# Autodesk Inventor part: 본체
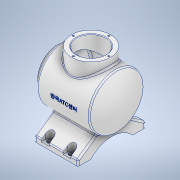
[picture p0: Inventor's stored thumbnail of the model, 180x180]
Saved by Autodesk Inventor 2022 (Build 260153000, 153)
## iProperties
Created: 2023-04
Part Number: 본체
Material: 알루미늄 6061
Document SubType Name: Modeling
Designer: Admin
Mass: 1296.69 g
Surface Area: 1060.41 cm^2
Volume: 480.256 cm^3
Density: 2.7 g/cm^3
Appearance: 알루미늄 - 평지
Author: Admin
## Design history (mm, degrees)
sketch "스케치1"
  geometry: L1 (-84.575, 0)-(87.453, 0) reference; L2 (0, -24.969)-(0, 149.813) reference; L3 (-60, 0)-(-60, 36); L4 (-60, 36)-(-48, 36); L5 (-48, 36)-(-48, 50); L6 (-48, 50)-(48.336, 50); L7 (60, 0)-(60, 124.844); L8 (-60, 0)-(60, 0); A1 r 113 centre (-53, 0) between (60, 0) and (48.336, 50); 1 further point
  constraints: 12 end point, 2 perpendicular, 2 point on circle, 2 point on line, 2 vertical, 1 centre point, 1 collinear, 1 horizontal, 1 tangent, 1 other
  dimensions: "d2" = 226 diameter of A1; "d3" = 120 distance from line of L7.start L3; "d4" = 108 distance from line of L7.start L5; "d5" = 72 diameter of L4 L1; "d6" = 100 diameter of L6 L1
revolve "회전1" sketch "스케치1" stored, may be unused: angle "d7" = 90 deg
node "작업 평면1"
sketch "스케치2"
  geometry: L1 (-38.5, -77)-(-62, -77); L2 (-62, -77)-(-62, -67); L3 (-62, -67)-(-15.04, -34.118); L4 (0, -144.515)-(0, 82.419) reference; L5 (62, -67)-(15.04, -34.118); L6 (62, -77)-(62, -67); L7 (38.5, -77)-(62, -77); L8 (-19.186, -60)-(22.433, -60); L9 (-86.8, 0)-(86.8, 0) reference; L10 (-15.04, -34.118)-(15.04, -34.118); A1 r 52.096 centre (0, -112.096) between (38.5, -77) and (-38.5, -77); 1 further point
  constraints: 16 end point, 4 symmetric about line, 3 horizontal, 2 point on circle, 1 centre point, 1 perpendicular, 1 tangent
  dimensions: "d9" = 10 distance of L1.end L2.end; "d10" = 77 distance of L7.start L1.start; "d11" = 55 deg angle of L6 L5; "d12" = 17 distance between parallel lines of L8 L7; "d13" = 124 distance between parallel lines of L6 L2; "d14" = 77 distance between parallel lines of L7 L9; "d15" = 42.88199 distance between parallel lines of L7 L10
extrude "돌출1" join sketch "스케치2" distance "d16" = 80; taper "d17" = 0 deg
node "작업 평면2"
sketch "스케치3"
  geometry: L1 (-44, -38.5)-(124, -38.5) reference; L2 (-20, -74.5)-(-20, -2.5) reference; C1 r 36 at (42, -38.5); 1 further point
  constraints: 1 centre point, 1 coincident, 1 point on line
  dimensions: "d19" = 72 diameter of C1; "d82" = 62 distance from line of point (42, -38.5) L2
extrude "돌출2" join sketch "스케치3" stored distance "d20" = 80; taper "d21" = 0 deg
sketch "스케치4"
  geometry: C1 r 36 at (0, 0) reference; C2 r 27 at (0, 0); 1 further point
  constraints: 1 centre point, 1 coincident
  dimensions: "d22" = 54 diameter of C2
extrude "돌출3" cut sketch "스케치4" distance "d23" = 60; taper "d24" = 0 deg
sketch "스케치5"
  geometry: L1 (-84, 0)-(84, 0) reference; L2 (-60, -36)-(-60, 36) reference; L3 (-60, 27)-(-41, 27); L4 (-41, 27)-(-41, 43); L5 (-41, 43)-(43.887, 43); L6 (-60, 27)-(-60, 0); L7 (-60, 0)-(53, 0); L8 (48.336, -50)-(48.336, 50) reference; A1 r 113 centre (-53, 0) between (48.336, -50) and (48.336, 50) reference; A2 r 106 centre (-53, 0) between (53, 0) and (43.887, 43); 1 further point
  constraints: 10 end point, 4 perpendicular, 2 point on circle, 2 point on line, 1 centre point, 1 midpoint
  dimensions: "d25" = 7 radial gap between concentric circles of A1 A2; "d26" = 54 diameter of L3 L1; "d27" = 19 distance of L3.start L3.end; "d28" = 86 diameter of L5 L1
revolve "회전2" sketch "스케치5" stored, may be unused: angle "d29" = 90 deg
node "작업 평면3"
sketch "스케치7"
  geometry: L1 (0, 0)-(80, 0) reference; L2 (0, 0)-(0, 23.5) reference; L3 (-44, 62)-(124, 62) reference; C1 r 4.5 at (20, 8); C2 r 4.5 at (60, 8); C3 r 4.5 at (20, 116); C4 r 4.5 at (60, 116); 1 further point
  constraints: 4 centre point, 2 symmetric about line, 2 other
  dimensions: "d37" = 8 distance from line of C1.centre L1; "d38" = 20 distance from line of C1.centre L2; "d39" = 9 diameter of C1; "d40" = 9 diameter of C2; "d41" = 8 distance from line of L1 C2.centre; "d42" = 40 distance of C2.centre C1.centre
extrude "돌출4" cut sketch "스케치7" distance "d43" = 6; taper "d44" = 0 deg
sketch "스케치8"
  geometry: L1 (-7, 0)-(-7, -8); L2 (-20, -8)-(60, -8) reference; L3 (7, 0)-(7, -8); L4 (-7, -8)-(7, -8); L5 (33, 0)-(33, -8); L6 (47, 0)-(47, -8); L7 (33, -8)-(47, -8); L8 (-64, 54)-(104, 54) reference; L9 (-7, -8)-(7, -8); L10 (-7, 108)-(-7, 116); L11 (7, 108)-(7, 116); L12 (33, 108)-(33, 116); L13 (47, 108)-(47, 116); L14 (-7, 116)-(7, 116); L15 (-20, 116)-(60, 116) reference; L16 (33, 116)-(47, 116); C1 r 4.5 at (0, 0) reference; C2 r 4.5 at (40, 0) reference; A1 r 7 centre (0, 0) between (7, 0) and (-7, 0); A2 r 7 centre (40, 0) between (47, 0) and (33, 0); A3 r 7 centre (0, 108) between (-7, 108) and (7, 108); A4 r 7 centre (40, 108) between (33, 108) and (47, 108); 1 further point
  constraints: 26 end point, 10 symmetric about line, 8 point on circle, 5 collinear, 4 centre point, 4 point on line, 4 tangent, 2 coincident, 2 parallel, 1 perpendicular, 1 vertical, 2 other
  dimensions: "d45" = 14 diameter of A1; "d46" = 14 diameter of A2
extrude "돌출5" cut sketch "스케치8" distance "d47" = 30; taper "d48" = 0 deg
sketch "스케치9" dims "d49" = 65
  geometry: L1 (0, -105.4)-(0, 93.4) reference; C1 r 27 at (0, 0) reference; 9 further points
  constraints: 3 coincident, 2 horizontal alignment, 2 vertical alignment, 1 point on line, 19 other
  dimensions: "d52" = 360 deg dimension on point (0, 0) point (0, 32.5) (derived)
hole "구멍1" sketch "스케치9" at (0, 32.5), (-32.5, 0), (0, -32.5), (32.5, 0) diameter "d54" = 3.242; stored, may be unused: countersink angle "d58" = 90 deg, drill point angle "d60" = 118 deg; dims "d55" = 8, "d56" = 4, "d57" = 2, "d59" = 10
fillet "모깎기1" dims "d73" = 3
fillet "모깎기2" dims "d74" = 3
chamfer "모따기1" distance "d75" = 1; stored, may be unused: second distance "d76" = 2, angle "d77" = 45 deg
node "작업 평면4"
sketch "스케치11"
  geometry: L1 (-60, -36)-(-60, 36) reference; L2 (-84, 0)-(84, 0) reference; 2 further points
  constraints: 1 point on line, 1 other
  dimensions: "d79" = 62 distance from line of point (2, 0) L1
feature "엠보싱1" sketch "스케치11" dims "d9" = 10, "d10" = 77, "d11" = 55 deg, "d12" = 17, "d13" = 124, "d14" = 77, "d15" = 42.88199, "d80" = 0.5, "d81" = 0
sketch "스케치12" dims "d83" = 65
  geometry: L1 (0, 0)-(0, 55.021); C1 r 36 at (0, 0) reference; 9 further points
  constraints: 3 coincident, 2 end point, 2 horizontal alignment, 2 vertical alignment, 1 point on line, 1 vertical, 19 other
  dimensions: "d86" = 360 deg dimension on point (0, 0) point (0, 32.5) (derived)
hole "구멍3" sketch "스케치12" at (0, 32.5), (-32.5, 0), (0, -32.5), (32.5, 0) diameter "d88" = 3.242; stored, may be unused: countersink angle "d92" = 90 deg, drill point angle "d94" = 118 deg; dims "d89" = 8, "d90" = 4, "d91" = 2, "d93" = 10
node "솔리드1"
feature "A9D066F2-1C7D-4E18-AEED-F7BC21143FA4" dims "d54" = 3.242, "d55" = 8, "d56" = 4, "d57" = 2, "d58" = 90 deg, "d59" = 10, "d60" = 118 deg
other parameters: "d18" = -142, "d30" = -27.5, "d78" = 136.5
